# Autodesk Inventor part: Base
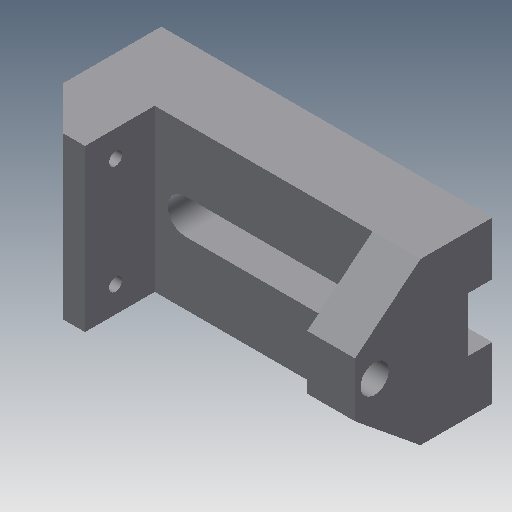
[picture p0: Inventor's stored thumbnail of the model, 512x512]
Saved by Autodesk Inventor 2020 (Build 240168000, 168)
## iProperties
Created: 2002-02
Part Number: Base
Document SubType Name: Modeling
Designer: ***
Density: 1 g/cm^3
Material: Generic
Appearance: Default
Control State: 0
Master: False
Checked Out: False
Shininess: 77.0
Length Units: 11269
Angle Units: 11279
Time Units: 11290
Mass Units: 11283
Length Display Precision: 3
Angle Display Precision: 2
Density: 0.0
Volumn: 0.0
Area: 0.0
PropertySet Name: Model Information
Author: ***
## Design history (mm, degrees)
sketch "Sketch2"
  geometry: L1 (-63.961, -4.254)-(-63.961, -37.254); L2 (-63.961, -37.254)-(88.039, -37.254); L3 (88.039, -37.254)-(88.039, 7.746); L4 (88.039, 7.746)-(68.039, 27.746); L5 (68.039, 27.746)-(58.039, 27.746); L6 (58.039, 27.746)-(58.039, -4.254); L7 (58.039, -4.254)-(-63.961, -4.254)
  constraints: 14 end point, 4 parallel, 1 perpendicular, 1 vertical
  dimensions: "d7" = 10 distance of L4.end L5.end; "d8" = 135 deg angle of L3 L4; "d9" = 33 distance of L1.start L1.end; "d10" = 152 distance of L1.end L2.end; "d11" = 65 distance between parallel lines of L5 L2; "d21" = 30 distance between parallel lines of L3 L6
extrude "Extrusion1" new body sketch "Sketch2" stored distance "d13" = 74; taper "d14" = 0 deg
sketch "Sketch3"
  geometry: L1 (0, 74)-(0, 0) reference; L2 (0, 0)-(-30, 24.5); L3 (-30, 24.5)-(-30, 49.5); L4 (-30, 49.5)-(0, 74); C1 r 6.5 at (-21, 37)
  constraints: 6 end point, 1 centre point, 1 equal length, 1 parallel
  dimensions: "d15" = 25 distance of L2.end L3.end; "d16" = 30 distance between parallel lines of L3 L1; "d17" = 13 diameter of C1; "d18" = 9 distance from line of L3 C1.centre
extrude "Extrusion2" join sketch "Sketch3" distance "d19" = 22; taper "d20" = 0 deg
sketch "Sketch4"
  geometry: L1 (0, 0)-(0, 74) reference; L2 (0, 0)-(45, 0) reference; C1 r 8 at (25, 37)
  constraints: 1 centre point
  dimensions: "d22" = 16 diameter of C1; "d23" = 25 distance from line of L1 C1.centre; "d24" = 37 distance from line of L2 C1.centre
extrude "Extrusion3" cut sketch "Sketch4" distance "d25" = 13; taper "d26" = 0 deg
sketch "Sketch5"
  geometry: L1 (45, 74)-(0, 74) reference; L2 (65, 0)-(65, 74) reference; 1 further point
  dimensions: "d27" = 12 distance from line of point (51, 62) L1; "d28" = 14 distance from line of L2 point (51, 62)
hole "Hole1" sketch "Sketch5" at (51, 62) diameter "d29" = 6; stored, may be unused: countersink angle "d33" = 82 deg, drill point angle "d35" = 0 deg; dims "d30" = 6, "d31" = 8, "d32" = 10, "d34" = 30
mirror "Mirror1"
sketch "Sketch6"
  geometry: L1 (100, 0)-(100, 74) reference; L2 (100, 74)-(0, 74) reference; L3 (14, 45)-(92, 45); L4 (92, 29)-(14, 29); A1 r 8 centre (92, 37) between (92, 29) and (92, 45); A2 r 8 centre (14, 37) between (14, 45) and (14, 29)
  constraints: 4 end point, 4 point on circle, 4 tangent, 2 centre point, 1 horizontal, 1 parallel
  dimensions: "d36" = 8 radius of A2; "d37" = 78 distance of L4.start L4.end; "d38" = 8 distance from line of L1 A1.centre; "d39" = 37 distance from line of L2 A2.centre
extrude "Extrusion4" cut sketch "Sketch6" extent not by distance; stored distance "d40" = 13; taper "d41" = 0 deg
sketch "Sketch7"
  geometry: L1 (0, 49.5)-(11, 49.5); L2 (11, 49.5)-(11, 24.5); L3 (11, 24.5)-(0, 24.5); L4 (0, 24.5)-(0, 49.5); L5 (45, 74)-(0, 74) reference; L6 (0, 0)-(0, 74) reference
  constraints: 8 end point, 2 parallel, 1 collinear, 1 horizontal, 1 perpendicular
  dimensions: "d42" = 25 distance of L3.end L1.start; "d43" = 11 distance of L1.start L1.end; "d44" = 24.5 distance between parallel lines of L5 L1
extrude "Extrusion5" cut sketch "Sketch7" extent not by distance; stored distance "d45" = 13; taper "d46" = 0 deg
body "Solid1"
